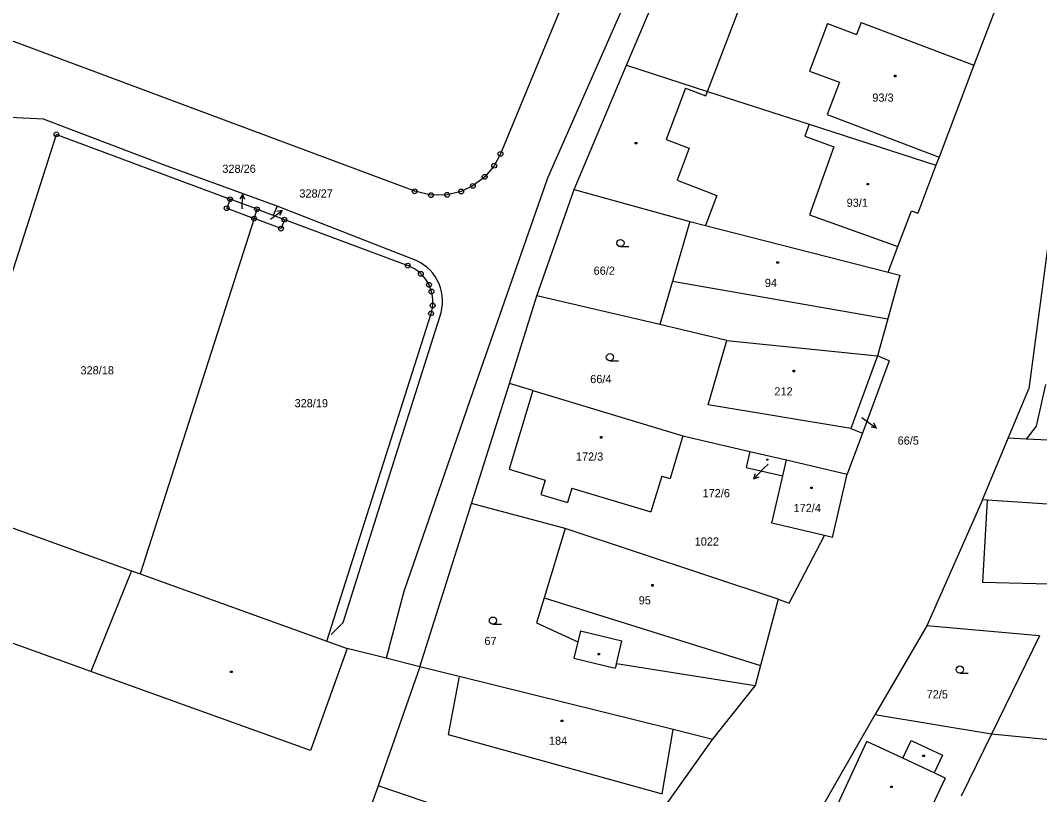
# Model space of a CAD drawing. Extents: x -770973 to -770265, y -1049936 to -1049427.
# Drawn here: x -770637.6 to -770531.6, y -1049867 to -1049786.5 of the extents above; entities that cross this region are included whole.
import ezdxf

# ---------------------------------------------------------------- set-up
doc = ezdxf.new("R2010")
doc.units = 0
for name, color, linetype in [('Vrstva 1', 7, 'Continuous'), ('Vrstva 13', 7, 'Continuous'), ('Vrstva 14', 7, 'Continuous'), ('Vrstva 15', 7, 'Continuous'), ('Vrstva 16', 7, 'Continuous'), ('Vrstva 2', 7, 'Continuous'), ('Vrstva 23', 7, 'Continuous'), ('Vrstva 25', 7, 'Continuous'), ('Vrstva 28', 7, 'Continuous'), ('Vrstva 50', 7, 'Continuous')]:
    doc.layers.add(name, color=color, linetype=linetype)

msp = doc.modelspace()

# ---------------------------------------------------------------- linework, layer by layer
at = {"layer": 'Vrstva 1'}
for p, q in [((-770596.58, -1049804.27), (-770708.79, -1049762.33)), ((-770574.55, -1049791.16), (-770569.18, -1049778.4)), ((-770572.91, -1049780.51), (-770582.76, -1049802.9)), ((-770579.83, -1049781.44), (-770587.66, -1049800.38)), ((-770535.14, -1049782.5), (-770538.43, -1049791.15)), ((-770580, -1049804.1), (-770574.55, -1049791.16)), ((-770574.55, -1049791.16), (-770566.12, -1049793.88)), ((-770538.43, -1049791.15), (-770542.06, -1049800.71)), ((-770566.12, -1049793.88), (-770555.57, -1049797.29)), ((-770555.57, -1049797.29), (-770542.38, -1049801.56)), ((-770646.07, -1049836.54), (-770633.83, -1049798.35)), ((-770633.83, -1049798.35), (-770615.78, -1049805.1)), ((-770587.66, -1049800.38), (-770588.32, -1049801.61)), ((-770542.06, -1049800.71), (-770542.38, -1049801.56)), ((-770588.32, -1049801.61), (-770589.3, -1049802.77)), ((-770542.38, -1049801.56), (-770544.28, -1049806.55)), ((-770589.3, -1049802.77), (-770590.53, -1049803.71)), ((-770582.76, -1049802.9), (-770590.24, -1049824.21)), ((-770529.77, -1049802.63), (-770532.71, -1049824.8)), ((-770594.88, -1049804.67), (-770596.58, -1049804.27)), ((-770593.21, -1049804.64), (-770594.88, -1049804.67)), ((-770591.75, -1049804.29), (-770593.21, -1049804.64)), ((-770590.53, -1049803.71), (-770591.75, -1049804.29)), ((-770583.88, -1049815.15), (-770580, -1049804.1)), ((-770580, -1049804.1), (-770567.99, -1049807.41)), ((-770615.78, -1049805.1), (-770616.13, -1049806.03)), ((-770612.97, -1049806.14), (-770615.78, -1049805.1)), ((-770616.13, -1049806.03), (-770613.28, -1049807.11)), ((-770613.28, -1049807.11), (-770612.97, -1049806.14)), ((-770612.97, -1049806.14), (-770610.13, -1049807.22)), ((-770546.34, -1049810.01), (-770544.93, -1049806.3)), ((-770544.93, -1049806.3), (-770544.28, -1049806.55)), ((-770613.28, -1049807.11), (-770625.12, -1049844.07)), ((-770610.48, -1049808.15), (-770613.28, -1049807.11)), ((-770610.13, -1049807.22), (-770610.48, -1049808.15)), ((-770610.13, -1049807.22), (-770597.3, -1049812)), ((-770567.99, -1049807.41), (-770569.78, -1049813.62)), ((-770567.99, -1049807.41), (-770566.35, -1049807.83)), ((-770566.35, -1049807.83), (-770547.36, -1049812.68)), ((-770547.36, -1049812.68), (-770546.34, -1049810.01)), ((-770546.15, -1049812.99), (-770547.4, -1049817.55)), ((-770547.36, -1049812.68), (-770546.15, -1049812.99)), ((-770594.83, -1049814.69), (-770595.09, -1049814)), ((-770569.78, -1049813.62), (-770571.09, -1049818.14)), ((-770586.74, -1049824.26), (-770583.88, -1049815.15)), ((-770571.09, -1049818.14), (-770583.88, -1049815.15)), ((-770605.7, -1049851.06), (-770594.88, -1049816.97)), ((-770564.12, -1049819.77), (-770571.09, -1049818.14)), ((-770547.4, -1049817.55), (-770548.45, -1049821.39)), ((-770566.08, -1049826.48), (-770564.12, -1049819.77)), ((-770564.12, -1049819.77), (-770548.45, -1049821.39)), ((-770548.45, -1049821.39), (-770551.23, -1049828.94)), ((-770547.26, -1049821.91), (-770548.45, -1049821.39)), ((-770547.26, -1049821.91), (-770550.03, -1049829.42)), ((-770590.24, -1049824.21), (-770597.7, -1049845.9)), ((-770590.66, -1049836.74), (-770586.74, -1049824.26)), ((-770584.3, -1049824.99), (-770586.74, -1049824.26)), ((-770534.86, -1049829.96), (-770532.71, -1049824.8)), ((-770531, -1049824.37), (-770531.95, -1049828.71)), ((-770584.3, -1049824.99), (-770586.76, -1049833.18)), ((-770584.3, -1049824.99), (-770568.69, -1049829.7)), ((-770551.23, -1049828.94), (-770566.08, -1049826.48)), ((-770551.23, -1049828.94), (-770550.03, -1049829.42)), ((-770531.95, -1049828.71), (-770533.02, -1049830.05)), ((-770568.69, -1049829.7), (-770570.03, -1049834.15)), ((-770568.69, -1049829.7), (-770561.72, -1049831.32)), ((-770550.03, -1049829.42), (-770551.6, -1049833.69)), ((-770537.53, -1049836.35), (-770534.86, -1049829.96)), ((-770533.02, -1049830.05), (-770534.86, -1049829.96)), ((-770521.81, -1049830.6), (-770533.02, -1049830.05)), ((-770561.72, -1049831.32), (-770562.11, -1049832.98)), ((-770561.72, -1049831.32), (-770557.93, -1049832.21)), ((-770558.31, -1049833.86), (-770557.93, -1049832.21)), ((-770557.93, -1049832.21), (-770551.6, -1049833.69)), ((-770586.76, -1049833.18), (-770583.03, -1049834.31)), ((-770562.11, -1049832.98), (-770558.31, -1049833.86)), ((-770583.03, -1049834.31), (-770583.48, -1049835.79)), ((-770570.89, -1049833.89), (-770572.02, -1049837.62)), ((-770570.89, -1049833.89), (-770570.03, -1049834.15)), ((-770559.46, -1049838.78), (-770558.31, -1049833.86)), ((-770553.13, -1049840.26), (-770551.6, -1049833.69)), ((-770580.25, -1049835.14), (-770580.7, -1049836.63)), ((-770580.25, -1049835.14), (-770572.02, -1049837.62)), ((-770583.48, -1049835.79), (-770580.7, -1049836.63)), ((-770537.53, -1049836.35), (-770543.34, -1049849.46)), ((-770537.07, -1049836.38), (-770537.53, -1049836.35)), ((-770519.27, -1049837.56), (-770537.07, -1049836.38)), ((-770646.07, -1049836.54), (-770626.01, -1049843.75)), ((-770596.05, -1049853.72), (-770590.66, -1049836.74)), ((-770580.95, -1049839.35), (-770590.66, -1049836.74)), ((-770580.95, -1049839.35), (-770583.13, -1049846.55)), ((-770558.78, -1049846.69), (-770580.95, -1049839.35)), ((-770553.97, -1049840.07), (-770559.46, -1049838.78)), ((-770557.63, -1049847.1), (-770553.97, -1049840.07)), ((-770553.13, -1049840.26), (-770553.97, -1049840.07)), ((-770626.01, -1049843.75), (-770625.12, -1049844.07)), ((-770625.12, -1049844.07), (-770605.7, -1049851.06)), ((-770597.7, -1049845.9), (-770599.53, -1049852.84)), ((-770583.13, -1049846.55), (-770583.91, -1049849.15)), ((-770558.78, -1049846.69), (-770560.61, -1049853.59)), ((-770558.78, -1049846.69), (-770557.63, -1049847.1)), ((-770583.91, -1049849.15), (-770579.61, -1049851.11)), ((-770543.34, -1049849.46), (-770548.75, -1049858.73)), ((-770531.61, -1049850.5), (-770543.34, -1049849.46)), ((-770605.7, -1049851.06), (-770603.6, -1049851.81)), ((-770579.61, -1049851.11), (-770580.03, -1049852.82)), ((-770531.61, -1049850.5), (-770536.61, -1049860.73)), ((-770599.53, -1049852.84), (-770603.6, -1049851.81)), ((-770596.05, -1049853.72), (-770599.53, -1049852.84)), ((-770580.03, -1049852.82), (-770575.73, -1049853.88)), ((-770575.61, -1049853.4), (-770575.73, -1049853.88)), ((-770561.17, -1049855.69), (-770575.61, -1049853.4)), ((-770596.05, -1049853.72), (-770600.39, -1049866.1)), ((-770591.96, -1049854.73), (-770596.05, -1049853.72)), ((-770560.61, -1049853.59), (-770561.17, -1049855.69)), ((-770569.71, -1049860.25), (-770591.96, -1049854.73)), ((-770565.62, -1049861.27), (-770561.17, -1049855.69)), ((-770548.75, -1049858.73), (-770554.96, -1049869.59)), ((-770536.61, -1049860.73), (-770548.75, -1049858.73)), ((-770565.62, -1049861.27), (-770569.71, -1049860.25)), ((-770536.61, -1049860.73), (-770539.76, -1049867.18)), ((-770522.27, -1049862.11), (-770536.61, -1049860.73)), ((-770574.15, -1049873.29), (-770565.62, -1049861.27)), ((-770600.39, -1049866.1), (-770602.87, -1049873.18)), ((-770591.32, -1049869.17), (-770600.39, -1049866.1))]:
    msp.add_line(p, q, dxfattribs=at)
for centre, radius, start, end in [((-770598.73, -1049815.8), 4.06, 26.3302, 69.381), ((-770598.73, -1049815.75), 4.04, 342.3326, 15.1549)]:
    msp.add_arc(centre, radius, start, end, dxfattribs=at)
at = {"layer": 'Vrstva 13'}
for p, q in [((-770550.09, -1049827.81), (-770549.8, -1049828.02)), ((-770559.84, -1049832.64), (-770560.27, -1049833.08))]:
    msp.add_line(p, q, dxfattribs=at)
at = {"layer": 'Vrstva 16'}
for p, q in [((-770614.5, -1049804.6), (-770614.76, -1049805.1)), ((-770614.53, -1049806.1), (-770614.5, -1049804.6)), ((-770614.5, -1049804.6), (-770614.26, -1049805.1)), ((-770611.57, -1049807.17), (-770610.37, -1049806.27)), ((-770610.37, -1049806.27), (-770610.92, -1049806.37)), ((-770610.37, -1049806.27), (-770610.62, -1049806.77)), ((-770549.8, -1049828.02), (-770548.58, -1049828.9)), ((-770548.58, -1049828.9), (-770549.13, -1049828.81)), ((-770548.58, -1049828.9), (-770548.84, -1049828.4)), ((-770560.27, -1049833.08), (-770561.31, -1049834.16)), ((-770561.31, -1049834.16), (-770561.14, -1049833.63)), ((-770561.31, -1049834.16), (-770560.78, -1049833.97))]:
    msp.add_line(p, q, dxfattribs=at)
at = {"layer": 'Vrstva 2'}
for p, q in [((-770566.12, -1049793.88), (-770561.35, -1049781.4)), ((-770553.65, -1049786.83), (-770555.52, -1049791.76)), ((-770553.65, -1049786.83), (-770550.65, -1049787.96)), ((-770550.17, -1049786.7), (-770550.65, -1049787.96)), ((-770550.17, -1049786.7), (-770538.43, -1049791.15)), ((-770555.52, -1049791.76), (-770552.42, -1049792.93)), ((-770552.42, -1049792.93), (-770553.69, -1049796.29)), ((-770568.41, -1049793.54), (-770570.45, -1049798.87)), ((-770568.41, -1049793.54), (-770566.3, -1049794.34)), ((-770566.3, -1049794.34), (-770566.12, -1049793.88)), ((-770553.69, -1049796.29), (-770542.06, -1049800.71)), ((-770555.57, -1049797.29), (-770556.02, -1049798.55)), ((-770570.45, -1049798.87), (-770568.03, -1049799.79)), ((-770556.02, -1049798.55), (-770553, -1049799.63)), ((-770568.03, -1049799.79), (-770569.3, -1049803.1)), ((-770553, -1049799.63), (-770555.53, -1049806.72)), ((-770569.3, -1049803.1), (-770565.15, -1049804.69)), ((-770565.15, -1049804.69), (-770566.35, -1049807.83)), ((-770555.53, -1049806.72), (-770546.34, -1049810.01)), ((-770569.78, -1049813.62), (-770547.4, -1049817.55)), ((-770537.07, -1049836.38), (-770537.54, -1049844.92)), ((-770626.01, -1049843.75), (-770630.25, -1049854.2)), ((-770537.54, -1049844.92), (-770519.49, -1049845.4)), ((-770583.13, -1049846.55), (-770560.61, -1049853.59)), ((-770630.25, -1049854.2), (-770649.88, -1049847.14)), ((-770579.33, -1049849.98), (-770579.61, -1049851.11)), ((-770579.33, -1049849.98), (-770575.03, -1049851.03)), ((-770575.61, -1049853.4), (-770575.03, -1049851.03)), ((-770603.6, -1049851.81), (-770607.41, -1049862.41)), ((-770607.41, -1049862.41), (-770630.25, -1049854.2)), ((-770591.96, -1049854.73), (-770593.09, -1049860.77)), ((-770593.09, -1049860.77), (-770570.84, -1049866.95)), ((-770570.84, -1049866.95), (-770569.71, -1049860.25)), ((-770553.32, -1049869.61), (-770549.58, -1049861.49)), ((-770545.83, -1049863.24), (-770549.58, -1049861.49)), ((-770545.83, -1049863.24), (-770544.96, -1049861.38)), ((-770544.96, -1049861.38), (-770541.71, -1049862.9)), ((-770541.71, -1049862.9), (-770542.58, -1049864.76)), ((-770542.58, -1049864.76), (-770545.83, -1049863.24)), ((-770541.43, -1049865.29), (-770542.58, -1049864.76)), ((-770541.43, -1049865.29), (-770545.19, -1049873.35))]:
    msp.add_line(p, q, dxfattribs=at)
at = {"layer": 'Vrstva 23'}
for p, q in [((-770575.19, -1049810.02), (-770574.31, -1049810.02)), ((-770576.28, -1049821.91), (-770575.4, -1049821.91)), ((-770588.44, -1049849.29), (-770587.56, -1049849.29)), ((-770539.9, -1049854.39), (-770539.02, -1049854.39))]:
    msp.add_line(p, q, dxfattribs=at)
for centre in [(-770575.19, -1049809.65), (-770576.28, -1049821.53), (-770588.44, -1049848.92), (-770539.9, -1049854.01)]:
    msp.add_circle(centre, 0.375, dxfattribs=at)
at = {"layer": 'Vrstva 25'}
for p, q in [((-770546.7, -1049792.21), (-770546.55, -1049792.21)), ((-770546.7, -1049792.36), (-770546.7, -1049792.21)), ((-770546.55, -1049792.36), (-770546.7, -1049792.36)), ((-770546.55, -1049792.21), (-770546.55, -1049792.36)), ((-770573.65, -1049799.2), (-770573.5, -1049799.2)), ((-770573.65, -1049799.35), (-770573.65, -1049799.2)), ((-770573.5, -1049799.35), (-770573.65, -1049799.35)), ((-770573.5, -1049799.2), (-770573.5, -1049799.35)), ((-770549.53, -1049803.45), (-770549.38, -1049803.45)), ((-770549.53, -1049803.6), (-770549.53, -1049803.45)), ((-770549.38, -1049803.6), (-770549.53, -1049803.6)), ((-770549.38, -1049803.45), (-770549.38, -1049803.6)), ((-770558.92, -1049811.59), (-770558.77, -1049811.59)), ((-770558.92, -1049811.74), (-770558.92, -1049811.59)), ((-770558.77, -1049811.74), (-770558.92, -1049811.74)), ((-770558.77, -1049811.59), (-770558.77, -1049811.74)), ((-770557.24, -1049822.88), (-770557.09, -1049822.88)), ((-770557.24, -1049823.03), (-770557.24, -1049822.88)), ((-770557.09, -1049823.03), (-770557.24, -1049823.03)), ((-770557.09, -1049822.88), (-770557.09, -1049823.03)), ((-770577.26, -1049829.78), (-770577.11, -1049829.78)), ((-770577.26, -1049829.93), (-770577.26, -1049829.78)), ((-770577.11, -1049829.93), (-770577.26, -1049829.93)), ((-770577.11, -1049829.78), (-770577.11, -1049829.93)), ((-770559.95, -1049832.14), (-770559.85, -1049832.14)), ((-770559.95, -1049832.24), (-770559.95, -1049832.14)), ((-770559.85, -1049832.24), (-770559.95, -1049832.24)), ((-770559.85, -1049832.14), (-770559.85, -1049832.24)), ((-770555.39, -1049835.03), (-770555.24, -1049835.03)), ((-770555.39, -1049835.18), (-770555.39, -1049835.03)), ((-770555.24, -1049835.18), (-770555.39, -1049835.18)), ((-770555.24, -1049835.03), (-770555.24, -1049835.18)), ((-770571.92, -1049845.18), (-770571.77, -1049845.18)), ((-770571.92, -1049845.33), (-770571.92, -1049845.18)), ((-770571.77, -1049845.33), (-770571.92, -1049845.33)), ((-770571.77, -1049845.18), (-770571.77, -1049845.33)), ((-770577.52, -1049852.33), (-770577.37, -1049852.33)), ((-770577.52, -1049852.48), (-770577.52, -1049852.33)), ((-770577.37, -1049852.33), (-770577.37, -1049852.48)), ((-770577.37, -1049852.48), (-770577.52, -1049852.48)), ((-770615.72, -1049854.18), (-770615.57, -1049854.18)), ((-770615.72, -1049854.33), (-770615.72, -1049854.18)), ((-770615.57, -1049854.33), (-770615.72, -1049854.33)), ((-770615.57, -1049854.18), (-770615.57, -1049854.33)), ((-770581.34, -1049859.26), (-770581.19, -1049859.26)), ((-770581.34, -1049859.41), (-770581.34, -1049859.26)), ((-770581.19, -1049859.41), (-770581.34, -1049859.41)), ((-770581.19, -1049859.26), (-770581.19, -1049859.41)), ((-770543.73, -1049862.9), (-770543.58, -1049862.9)), ((-770543.73, -1049863.05), (-770543.73, -1049862.9)), ((-770543.58, -1049862.9), (-770543.58, -1049863.05)), ((-770543.58, -1049863.05), (-770543.73, -1049863.05)), ((-770547.09, -1049866.12), (-770546.94, -1049866.12)), ((-770547.09, -1049866.27), (-770547.09, -1049866.12)), ((-770546.94, -1049866.12), (-770546.94, -1049866.27)), ((-770546.94, -1049866.27), (-770547.09, -1049866.27))]:
    msp.add_line(p, q, dxfattribs=at)
at = {"layer": 'Vrstva 28'}
for centre, radius in [((-770633.83, -1049798.35), 0.25), ((-770633.83, -1049798.35), 0.005), ((-770587.66, -1049800.38), 0.25), ((-770587.66, -1049800.38), 0.005), ((-770588.32, -1049801.61), 0.25), ((-770589.3, -1049802.77), 0.25), ((-770588.32, -1049801.61), 0.005), ((-770590.53, -1049803.71), 0.25), ((-770589.3, -1049802.77), 0.005), ((-770596.58, -1049804.27), 0.25), ((-770596.58, -1049804.27), 0.005), ((-770594.88, -1049804.67), 0.25), ((-770594.88, -1049804.67), 0.005), ((-770593.21, -1049804.64), 0.25), ((-770593.21, -1049804.64), 0.005), ((-770591.75, -1049804.29), 0.25), ((-770591.75, -1049804.29), 0.005), ((-770590.53, -1049803.71), 0.005), ((-770615.78, -1049805.1), 0.25), ((-770615.78, -1049805.1), 0.005), ((-770616.13, -1049806.03), 0.25), ((-770616.13, -1049806.03), 0.005), ((-770612.97, -1049806.14), 0.25), ((-770612.97, -1049806.14), 0.005), ((-770613.28, -1049807.11), 0.25), ((-770613.28, -1049807.11), 0.005), ((-770610.13, -1049807.22), 0.25), ((-770610.13, -1049807.22), 0.005), ((-770610.48, -1049808.15), 0.25), ((-770610.48, -1049808.15), 0.005), ((-770597.3, -1049812), 0.25), ((-770597.3, -1049812), 0.005), ((-770595.94, -1049812.85), 0.25), ((-770595.94, -1049812.85), 0.005), ((-770595.09, -1049814), 0.25), ((-770595.09, -1049814), 0.005), ((-770594.83, -1049814.69), 0.25), ((-770594.83, -1049814.69), 0.005), ((-770594.71, -1049816.15), 0.25), ((-770594.71, -1049816.15), 0.005), ((-770594.88, -1049816.97), 0.25), ((-770594.88, -1049816.97), 0.005)]:
    msp.add_circle(centre, radius, dxfattribs=at)
at = {"layer": 'Vrstva 50'}
for p, q in [((-770635.16, -1049796.76), (-770638.67, -1049796.58)), ((-770622.42, -1049801.62), (-770635.16, -1049796.76)), ((-770610.89, -1049805.83), (-770622.42, -1049801.62)), ((-770610.89, -1049805.83), (-770611.3, -1049806.8)), ((-770596.43, -1049811.46), (-770610.89, -1049805.83)), ((-770598.54, -1049831.73), (-770593.98, -1049817.32)), ((-770604.02, -1049849.13), (-770598.54, -1049831.73)), ((-770605.26, -1049850.36), (-770604.02, -1049849.13))]:
    msp.add_line(p, q, dxfattribs=at)
msp.add_arc((-770598.35, -1049815.7), 4.66, 339.6956, 65.6829, dxfattribs=at)

# ---------------------------------------------------------------- texts
at = {"layer": 'Vrstva 14'}
for s, height, p in [('328/26', 0.05, (-770614.53, -1049806.1)), ('328/27', 0.05, (-770611.57, -1049807.17)), ('66/2', 0.85, (-770577.98, -1049812.95)), ('328/18', 0.85, (-770631.33, -1049823.31)), ('66/4', 0.85, (-770578.33, -1049824.22)), ('328/19', 0.85, (-770609.07, -1049826.73)), ('66/5', 0.05, (-770550.17, -1049827.81)), ('1022', 0.85, (-770567.47, -1049841.12)), ('67', 0.85, (-770589.33, -1049851.46)), ('72/5', 0.85, (-770543.35, -1049857.01))]:
    msp.add_text(s, height=height, dxfattribs=at).set_placement(p)
at = {"layer": 'Vrstva 15'}
for s, height, p in [('93/3', 0.85, (-770549, -1049794.95)), ('93/1', 0.85, (-770551.67, -1049805.88)), ('94', 0.85, (-770560.17, -1049814.22)), ('212', 0.85, (-770559.18, -1049825.5)), ('172/3', 0.85, (-770579.82, -1049832.28)), ('172/6', 0.05, (-770559.94, -1049832.64)), ('172/4', 0.85, (-770557.19, -1049837.63)), ('95', 0.85, (-770573.29, -1049847.23)), ('184', 0.85, (-770582.62, -1049861.83))]:
    msp.add_text(s, height=height, dxfattribs=at).set_placement(p)
at = {"layer": 'Vrstva 16'}
for s, p in [('328/26', (-770616.58, -1049802.35)), ('328/27', (-770608.57, -1049804.92)), ('66/5', (-770546.37, -1049830.62)), ('172/6', (-770566.65, -1049836.09))]:
    msp.add_text(s, height=0.85, dxfattribs=at).set_placement(p)

doc.saveas('drawing.dxf')
